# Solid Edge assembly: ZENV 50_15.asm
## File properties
Title: Zylinder
Author: ahadarics
Template: iso metric assembly.asm
Last saved by: ahadarics
Revision: 11
Application: Solid Edge
Username: ahadarics
Dokumentum tartalom típus: 1
Document Number: ZENV 50/15
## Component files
Profilrohr.par
Kolbenstange.par
Kit_1.par
Kit_2.par
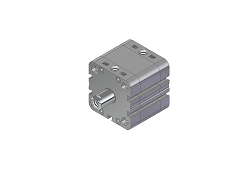
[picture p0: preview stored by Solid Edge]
